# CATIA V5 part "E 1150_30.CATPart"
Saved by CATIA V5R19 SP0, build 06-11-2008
Nomenclature: E 1150_30
Description: PART-E 1150_30-DESC
Property "Material": "1.7131 ~ 60 HRC"
Property "Hersteller": "Meusburger"
Property "Bestellnummer": "E 1150/30"
Property "Teilenummer": "E 1150/30"
Property "Beschreibung": "Führungsbuchse für Ausstoßerführung _ Guide bush for pusher guide"
Material "Steel": density 7860 kg/m3, Young's modulus 2e+11 Pa, Poisson ratio 0.266, thermal expansion 1.17e-05 1/K
Bounding box of the stored display mesh (mm): x -34 to 34, y -33.99 to 33.99, z -20 to 26
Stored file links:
  G:\UTB\Kombinované\Bakalářská práce\Catia\FORMA\E 1150_30.CATPart
  D:\Aplikace\CATIA\Nová složka\win_b64\startup\materials\Catalog.CATMaterial
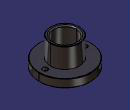
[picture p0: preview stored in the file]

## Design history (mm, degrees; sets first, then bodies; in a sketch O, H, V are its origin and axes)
Body1 "E 1150_30" (main body)
  Solid1: solid without history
